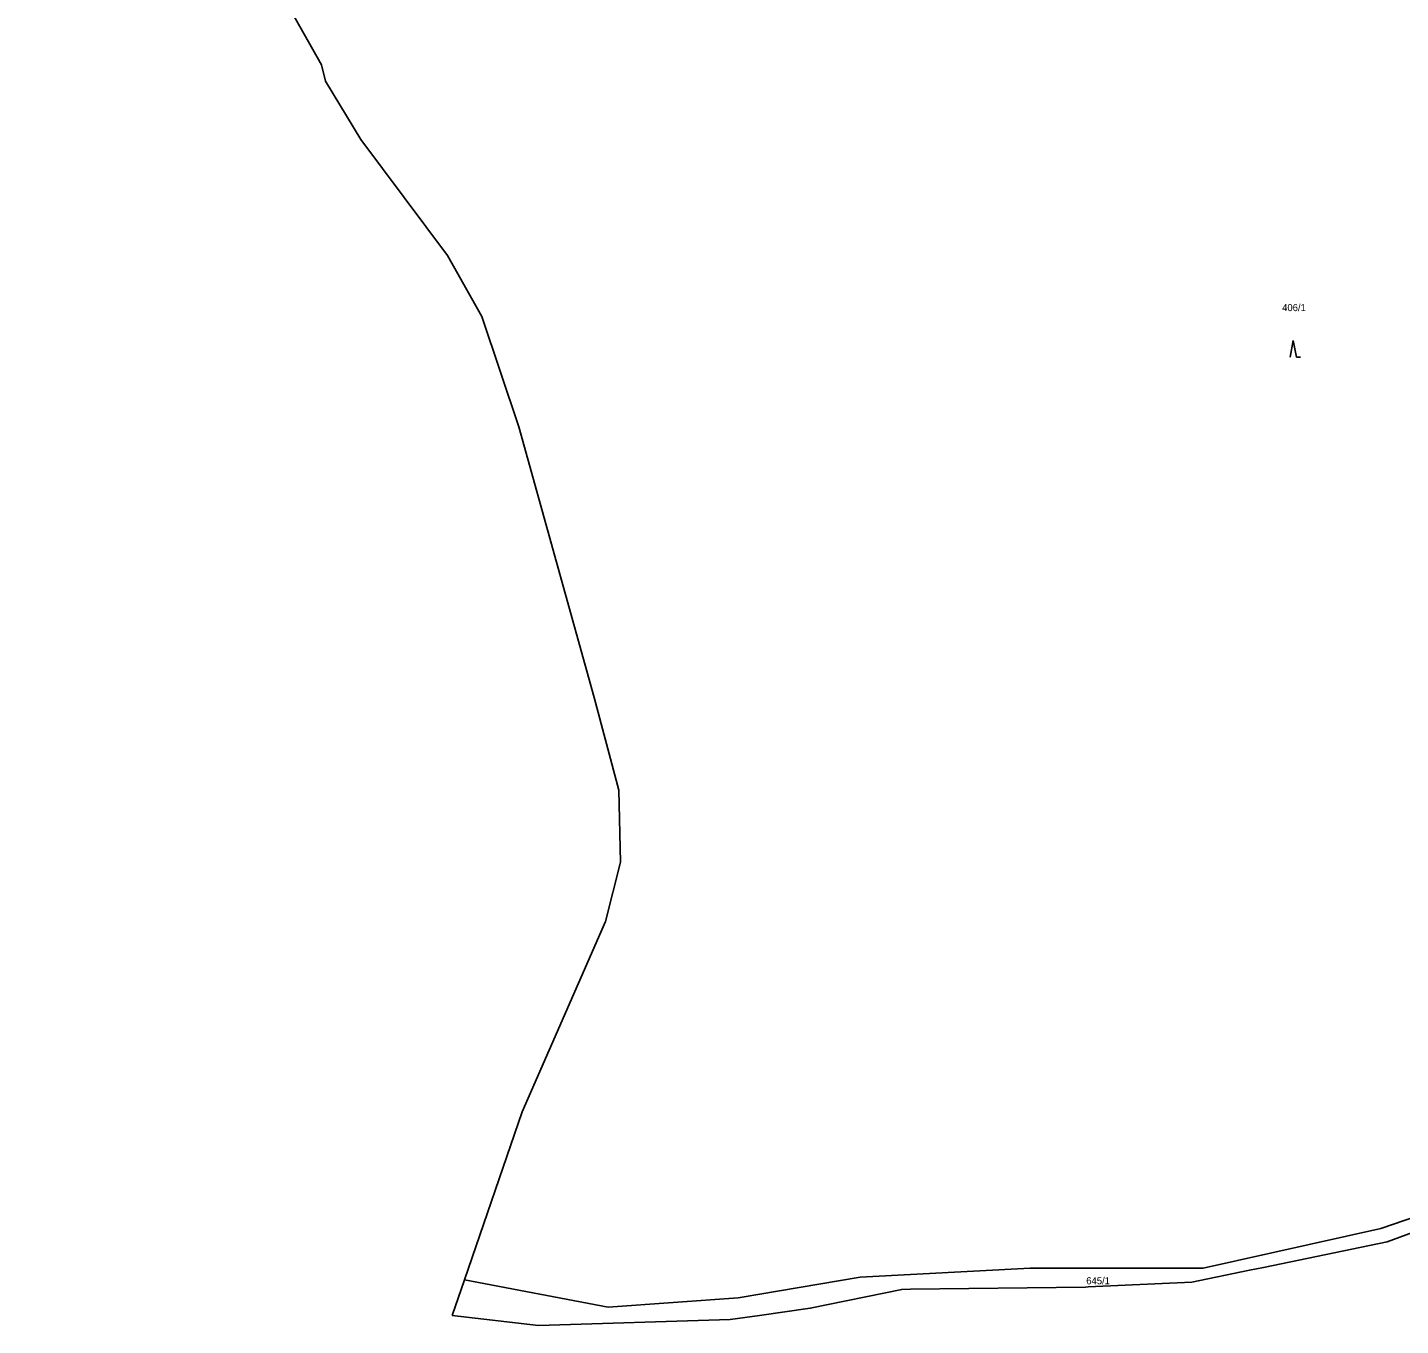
# Model space of a CAD drawing. Extents: x -744566 to -741843, y -1128407 to -1126744.
# Drawn here: x -744565.5 to -744236.2, y -1127584.5 to -1127273.4 of the extents above; entities that cross this region are included whole.
import ezdxf

# ---------------------------------------------------------------- set-up
doc = ezdxf.new("R2010")
doc.units = 0
for name, color, linetype in [('Hranice parcel', 7, 'Continuous'), ('Parcelní čísla', 7, 'Continuous'), ('Značky kultur', 7, 'Continuous')]:
    doc.layers.add(name, color=color, linetype=linetype)

msp = doc.modelspace()

# ---------------------------------------------------------------- linework, layer by layer
at = {"layer": 'Hranice parcel'}
for p, q in [((-744493.99, -1127286.26), (-744494.99, -1127282.31)), ((-744485.52, -1127300.23), (-744493.99, -1127286.26)), ((-744485.52, -1127300.23), (-744464.77, -1127328.01)), ((-744464.77, -1127328.01), (-744456.52, -1127342.64)), ((-744239.37, -1127564.46), (-744223.95, -1127558.72)), ((-744269.08, -1127570.59), (-744239.37, -1127564.46)), ((-744272.39, -1127571.27), (-744269.08, -1127570.59)), ((-744460.69, -1127573.57), (-744463.62, -1127582.08)), ((-744353.71, -1127575.84), (-744311.75, -1127575.29)), ((-744311.75, -1127575.29), (-744311.09, -1127575.26)), ((-744463.62, -1127582.08), (-744442.97, -1127584.52)), ((-744442.97, -1127584.52), (-744397, -1127583.1)), ((-744397, -1127583.1), (-744389.95, -1127582.1))]:
    msp.add_line(p, q, dxfattribs=at)
for points in [[(-744494.99, -1127282.31), (-744504.33, -1127265.74), (-744523.9, -1127156.29), (-744565.51, -1127108.73), (-744552.08, -1127062.86), (-744558.53, -1127054.28)], [(-744456.52, -1127342.64), (-744447.69, -1127369.09), (-744429.62, -1127433.96)], [(-744429.62, -1127433.96), (-744423.64, -1127456.16), (-744423.24, -1127473.47), (-744426.9, -1127487.71)], [(-744426.9, -1127487.71), (-744446.84, -1127533.33), (-744460.69, -1127573.57)], [(-744460.69, -1127573.57), (-744426.24, -1127580.1), (-744395.07, -1127577.86), (-744365.75, -1127572.94), (-744325.02, -1127570.79), (-744283.5, -1127570.77), (-744240.92, -1127561.26), (-744232.26, -1127558.32)], [(-744311.09, -1127575.26), (-744286.2, -1127574.12), (-744272.39, -1127571.27)], [(-744389.95, -1127582.1), (-744377.76, -1127580.37), (-744355.83, -1127575.87), (-744353.71, -1127575.84)]]:
    msp.add_lwpolyline(points, dxfattribs=at)
at = {"layer": 'Značky kultur'}
for p, q in [((-744261.92, -1127348.37), (-744262.67, -1127352.37)), ((-744261.17, -1127352.37), (-744261.92, -1127348.37)), ((-744261.17, -1127352.37), (-744260.174, -1127352.37))]:
    msp.add_line(p, q, dxfattribs=at)

# ---------------------------------------------------------------- texts
at = {"layer": 'Parcelní čísla'}
for s, p in [('406/1', (-744264.58, -1127341.36)), ('645/1', (-744311.563, -1127574.63))]:
    msp.add_text(s, height=1.7, dxfattribs=at).set_placement(p)

doc.saveas('drawing.dxf')
